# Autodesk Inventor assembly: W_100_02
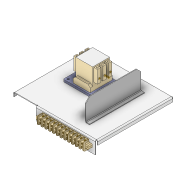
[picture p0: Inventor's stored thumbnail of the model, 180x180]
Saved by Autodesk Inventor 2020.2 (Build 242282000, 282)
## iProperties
Created: 2014-09
Part Number: W_100_02
Document SubType Name: Assembly
Designer: F.Stasiak
Catalog Web Link: www.expertbooks.pl
Manager: www.cadconsulting.pl
Company: Fabian Stasiak CAD Consulting
Author: F.Stasiak
Subject: Zbiór ćwiczeń. Autodesk Inventor 2020. Kurs Professional
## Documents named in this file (6)
- C:\2020_Kurs_Professional\R2 Wiązki\W_100_02.iam
- C:\2020_Kurs_Professional\R2 Wiązki\Komponenty\LISTWA_100_01.ipt
- C:\2020_Kurs_Professional\R2 Wiązki\Komponenty\S_150_100.ipt
- C:\2020_Kurs_Professional\R2 Wiązki\Komponenty\Podstawa_300_01.ipt
- C:\2020_Kurs_Professional\R2 Wiązki\Komponenty\Ściana_01.ipt
- C:\2020_Kurs_Professional\R2 Wiązki\Komponenty\BlackBox_300.ipt
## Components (5 placed, 5 different names)
1. S_150_100:1 — Zestawiający:2
2. LISTWA_100_01:1 — Zestawiający:1, Równoległy:2
3. Podstawa_300_01:1 — Równoległy:1, Zestawiający:1, Równoległy:2, Zestawiający:2, Zestawiający:3, Równoległy:4, Równoległy:5, Równoległy:9
4. Ściana_01:1 — Zestawiający:3, Równoległy:4, Równoległy:5
5. BlackBox_300:1 — Równoległy:9
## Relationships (8: Flush 5, Mate 3)
- Równoległy:1 [Flush]: Podstawa_300_01:1
- Zestawiający:1 [Mate]: LISTWA_100_01:1 ↔ Podstawa_300_01:1
- Równoległy:2 [Flush]: LISTWA_100_01:1 ↔ Podstawa_300_01:1
- Zestawiający:2 [Mate]: S_150_100:1 ↔ Podstawa_300_01:1
- Zestawiający:3 [Mate]: Podstawa_300_01:1 ↔ Ściana_01:1
- Równoległy:4 [Flush]: Podstawa_300_01:1 ↔ Ściana_01:1
- Równoległy:5 [Flush]: Podstawa_300_01:1 ↔ Ściana_01:1
- Równoległy:9 [Flush]: Podstawa_300_01:1 ↔ BlackBox_300:1
